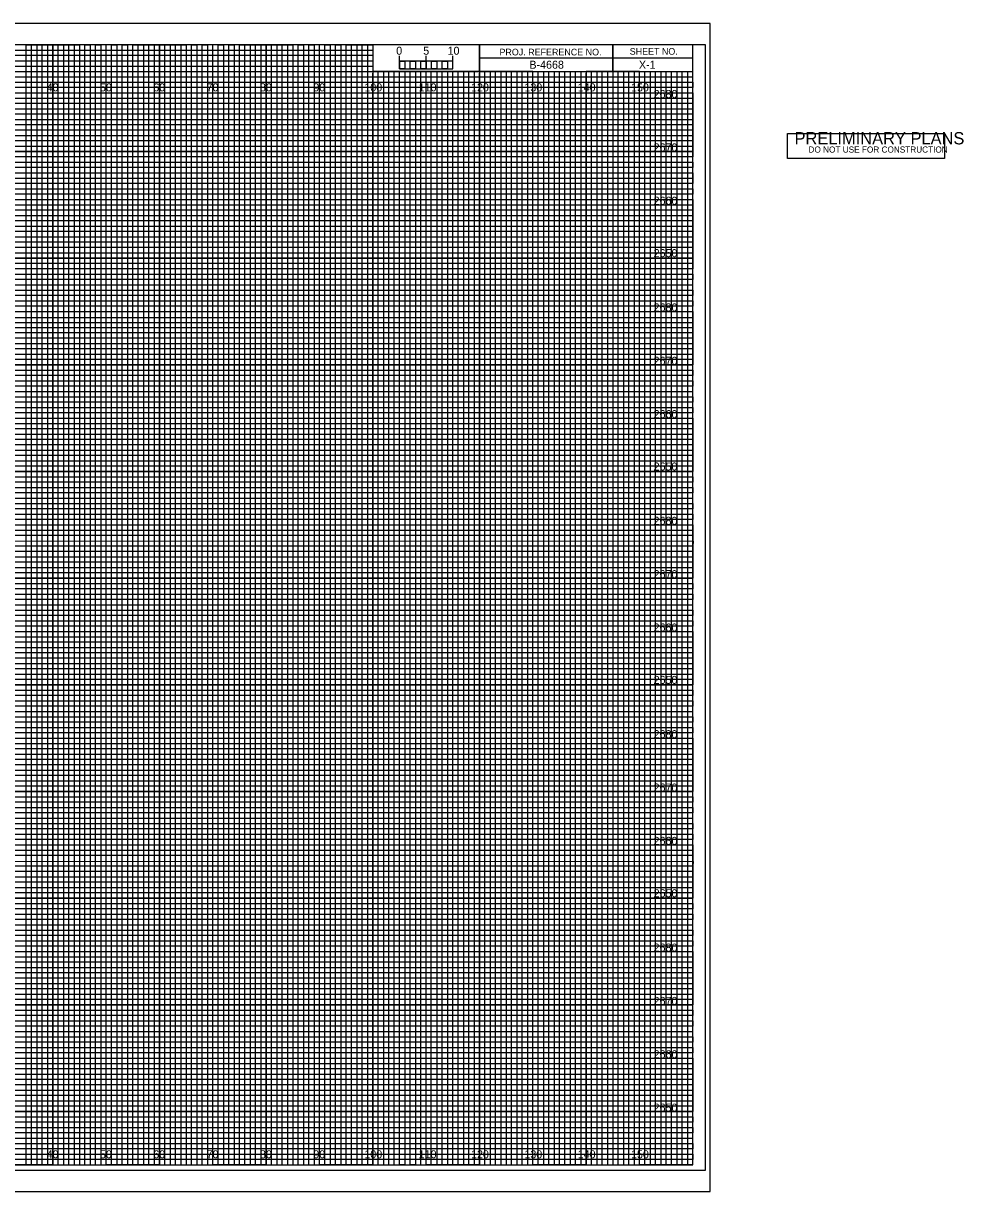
# Model space of a CAD drawing. Extents: x -13 to 371, y -5 to 214.
# Drawn here: x 194.5 to 370.8, y -5 to 214 of the extents above; entities that cross this region are included whole.
import ezdxf

# ---------------------------------------------------------------- set-up
doc = ezdxf.new("R2010")
doc.units = 0
for name, color, linetype in [('Exist Cross Section Cell', 7, 'Continuous'), ('Exist XS Center Line Elevation Label', 7, 'Continuous'), ('Exist XS Ground Line', 7, 'Continuous'), ('Prop XS Bridge', 7, 'Continuous'), ('Prop XS Ditch Slope Text', 7, 'Continuous'), ('Prop XS Ditch Standard Text', 7, 'Continuous'), ('Prop XS Dump Level', 7, 'Continuous'), ('Prop XS EOT Tick Mark', 7, 'Continuous'), ('Prop XS Finish Grade', 7, 'Continuous'), ('Prop XS Finish Grade Earthwork', 7, 'Continuous'), ('Prop XS Pvmt Edge Slope', 7, 'Continuous'), ('Prop XS SE Text', 7, 'Continuous'), ('Prop XS Side Slope Text', 7, 'Continuous'), ('Prop XS SS Elevation Text', 7, 'Continuous'), ('Prop XS Subgrade Earthwork', 7, 'Continuous'), ('Prop XS Vertical Lines', 7, 'Continuous')]:
    doc.layers.add(name, color=color, linetype=linetype)

msp = doc.modelspace()

# ---------------------------------------------------------------- linework, layer by layer
at = {"layer": 'Exist XS Center Line Elevation Label'}
for points in [[(185, 0), (195, 0), (195, 210), (205, 210), (205, 0), (215, 0), (215, 210), (225, 210), (225, 0), (235, 0), (235, 210), (245, 210), (245, 0), (255, 0), (255, 210), (259.93, 210), (260, 210), (260, 205), (264.99, 205), (264.99, 0), (275, 0), (275, 205), (285, 205), (285, 0), (295, 0), (295, 205), (305, 205), (305, 0), (315, 0), (315, 205)], [(0, 205), (275, 205)], [(0, 185), (320, 185), (320, 195), (0, 195)], [(0, 165), (320, 165), (320, 175), (0, 175)], [(0, 145), (320, 145), (320, 155), (0, 155)], [(0, 125), (320, 125), (320, 135), (0, 135)], [(0, 105), (320, 105), (320, 115), (0, 115)], [(0, 85), (320, 85), (320, 95), (0, 95)], [(0, 65), (320, 65), (320, 75), (0, 75)], [(0, 45), (320, 45), (320, 55), (0, 55)], [(0, 25), (320, 25), (320, 35), (0, 35)], [(0, 5), (320, 5), (320, 15), (0, 15)]]:
    msp.add_lwpolyline(points, dxfattribs=at)
at = {"layer": 'Exist XS Ground Line'}
for p, q in [((210, 210), (200, 210)), ((200, 210), (200, 0)), ((210, 0), (210, 210)), ((230, 210), (220, 210)), ((220, 210), (220, 0)), ((230, 0), (230, 210)), ((250, 210), (240, 210)), ((240, 210), (240, 0)), ((250, 0), (250, 210)), ((260, 210), (260, 0)), ((270, 0), (270, 205)), ((290, 205), (280, 205)), ((280, 205), (280, 0)), ((290, 0), (290, 205)), ((310, 205), (300, 205)), ((300, 205), (300, 0)), ((310, 0), (310, 205)), ((200, 0), (190, 0)), ((220, 0), (210, 0)), ((240, 0), (230, 0)), ((260, 0), (250, 0)), ((280, 0), (270, 0)), ((300, 0), (290, 0)), ((320, 0), (310, 0)), ((320, 0), (320, 0))]:
    msp.add_line(p, q, dxfattribs=at)
for points in [[(0, 200), (320, 200), (320, 190), (0, 190)], [(0, 180), (320, 180), (320, 170), (0, 170)], [(0, 160), (320, 160), (320, 150), (0, 150)], [(0, 140), (320, 140), (320, 130), (0, 130)], [(0, 120), (320, 120), (320, 110), (0, 110)], [(0, 100), (320, 100), (320, 90), (0, 90)], [(0, 80), (320, 80), (320, 70), (0, 70)], [(0, 60), (320, 60), (320, 50), (0, 50)], [(0, 40), (320, 40), (320, 30), (0, 30)], [(0, 20), (320, 20), (320, 10), (0, 10)]]:
    msp.add_lwpolyline(points, dxfattribs=at)
at = {"layer": 'Prop XS Ditch Slope Text'}
msp.add_lwpolyline([(-10.8, -1), (322.4, -1), (322.4, 210), (-10.8, 210)], close=True, dxfattribs=at)
at = {"layer": 'Prop XS Ditch Standard Text'}
msp.add_lwpolyline([(-13.4, -5), (323.3, -5), (323.3, 214), (-13.4, 214)], close=True, dxfattribs=at)
at = {"layer": 'Prop XS Dump Level'}
for p, q in [((0, 209), (260, 209)), ((260, 209), (260, 207.98)), ((260, 207.98), (0, 207.98)), ((0, 207), (260, 207)), ((260, 205.89), (0, 205.89)), ((260, 207), (260, 205.89)), ((0, 204), (320, 204))]:
    msp.add_line(p, q, dxfattribs=at)
for points in [[(0, 203), (270, 203), (320, 203), (320, 202), (0, 202)], [(0, 201), (320, 201), (320, 199), (0, 199)], [(0, 198), (320, 198), (320, 197), (0, 196.98)], [(0, 196), (320, 196), (320, 194), (0, 194)], [(0, 193), (320, 193), (320, 192), (0, 192)], [(0, 191), (320, 191), (320, 189), (0, 189)], [(0, 188), (320, 188), (320, 187), (0, 187)], [(0, 186), (320, 186), (320, 184), (0, 184)], [(0, 183), (320, 183), (320, 182), (0, 182)], [(0, 181), (320, 181), (320, 179), (0, 179)], [(0, 178), (320, 178), (320, 177), (0, 177)], [(0, 176), (320, 176), (320, 173.95), (320, 173), (320, 172), (0, 172)], [(0, 174), (320, 174), (320, 173), (0, 173)], [(0, 171), (320, 171), (320, 169), (0, 169.03)], [(0, 169.03), (320, 169), (320, 168), (0, 168)], [(0, 167), (320, 167), (320, 166), (0, 166)], [(0, 164), (320, 164), (320, 163), (0, 163)], [(0, 162), (320, 162), (320, 161), (0, 161)], [(-0.07, 158.89), (320, 158.89), (320, 157.88), (-0.07, 157.88)], [(0, 157), (320, 157), (320, 156), (0, 156)], [(0, 154), (320, 154), (320, 153), (0, 153)], [(0, 152), (320, 152), (320, 151), (0, 151)], [(0, 149), (320, 149), (320, 148), (0, 148)], [(0, 147), (320, 147), (320, 146), (0, 146)], [(0, 144), (320, 144), (320, 143), (0, 143)], [(0, 142), (320, 142), (320, 141), (0, 141)], [(0, 139), (320, 139), (319.99, 137.98), (0, 138)], [(0, 137), (320, 137), (320, 136), (0, 136)], [(0, 134), (320, 134), (320, 133), (0, 133)], [(0, 132), (320, 132), (320, 131), (0, 131)], [(0, 129), (320, 129), (320, 128), (0, 128)], [(0, 127), (320, 127), (320, 126), (0, 126)], [(0, 124), (320, 124), (320, 123), (0, 123)], [(0, 122), (320, 122), (320, 121), (0, 121)], [(0, 119), (320, 119), (320, 118), (0, 118)], [(0, 116.99), (320.07, 116.91), (320, 116), (0, 116)], [(0, 114), (320, 114), (320, 113), (0, 113)], [(0, 112), (320, 112), (320, 111), (0, 111)], [(0, 109), (320, 109), (320, 108), (0, 108)], [(0, 107), (320, 107), (320, 106), (0, 106)], [(0, 104), (320, 104), (320, 103), (0, 103)], [(0, 102), (320, 102), (320, 101), (0, 101)], [(0, 99), (320, 99), (320, 98), (0, 98)], [(0, 97), (320, 97), (320, 96), (0, 96)], [(0, 94), (320, 94), (320, 93), (0, 93)], [(0, 92), (320, 92), (320, 91), (0, 91)], [(0, 89), (320, 89), (320, 88), (0, 88)], [(0, 87), (320, 87), (320, 86), (0, 86)], [(0, 84), (320, 84), (320, 83), (0, 83)], [(0, 82), (320, 82), (320, 81), (0, 81)], [(0, 79), (320, 79), (319.99, 77.98), (0, 78)], [(0, 77), (320, 77), (320, 76), (0, 76)], [(0, 74), (320, 74), (320, 73), (0, 73)], [(0, 72), (320, 72), (320, 71), (0, 71)], [(0, 69), (320, 69), (320, 68), (0, 68)], [(0, 67), (320, 67), (320, 66), (0, 66)], [(0, 64), (320, 64), (320, 63), (0, 63)], [(0, 62), (320, 62), (320, 61), (0, 61)], [(0, 59), (320, 59), (320, 58), (0, 58)], [(0, 56.99), (320.07, 56.91), (320, 56), (0, 56)], [(0, 54), (320, 54), (320, 53), (0, 53)], [(0, 52), (320, 52), (320, 51), (0, 51)], [(0, 49), (320, 49), (320, 48), (0, 48)], [(0, 47), (320, 47), (320, 46), (0, 46)], [(0, 44), (320, 44), (320, 43), (0, 43)], [(0, 42), (320, 42), (320, 41), (0, 41)], [(0, 39), (320, 39), (320, 38), (0, 38)], [(0, 37), (320, 37), (320, 36), (0, 36)], [(0, 34), (320, 34), (320, 33), (0, 33)], [(0, 32), (320, 32), (320, 31), (0, 31)], [(0, 29), (320, 29), (320, 28), (0, 28)], [(0, 27), (320, 27), (320, 26), (0, 26)], [(0, 24), (320, 24), (320, 23), (0, 23)], [(0, 22), (320, 22), (320, 21), (0, 21)], [(0, 19), (320, 19), (320, 18), (0, 18)], [(0, 17), (320, 17), (320, 16), (0, 16)], [(0, 14), (320, 14), (320, 13), (0, 13)], [(0, 12), (320, 12), (320, 11), (0, 11)], [(0, 9), (320, 9), (320, 8), (0, 8)], [(0, 7), (320, 7), (320, 6), (0, 6)], [(0, 4), (320, 4), (320, 3), (0, 3)], [(0, 2), (320, 2), (320, 1), (0, 1)]]:
    msp.add_lwpolyline(points, dxfattribs=at)
at = {"layer": 'Prop XS Finish Grade Earthwork'}
for p, q in [((200, 0), (200, 210)), ((210, 0), (210, 210)), ((220, 0), (220, 210)), ((230, 0), (230, 210)), ((240, 0), (240, 210)), ((250, 0), (250, 210)), ((260, 0), (260, 204.69)), ((270, 0), (270, 204.69)), ((280, 0), (280, 204.69)), ((290, 0), (290, 204.69)), ((300, 0), (300, 204.69)), ((310, 0), (310, 204.69)), ((0, 200), (320, 200)), ((0, 190), (320, 190)), ((0, 180), (320, 180)), ((0, 170), (320, 170)), ((0, 160), (320, 160)), ((0, 150), (320, 150)), ((0, 140), (320, 140)), ((0, 130), (320, 130)), ((0, 120), (320, 120)), ((0, 110), (320, 110)), ((0, 100), (320, 100)), ((0, 90), (320, 90)), ((0, 80), (320, 80)), ((0, 70), (320, 70)), ((0, 60), (320, 60)), ((0, 50), (320, 50)), ((0, 40), (320, 40)), ((0, 30), (320, 30)), ((0, 20), (320, 20)), ((0, 10), (320, 10))]:
    msp.add_line(p, q, dxfattribs=at)
at = {"layer": 'Prop XS SE Text'}
for p, q in [((305, 210), (305, 205)), ((305, 205), (305, 210)), ((280, 207.5), (280, 205)), ((320, 207.49), (280, 207.49)), ((280, 205), (320, 205))]:
    msp.add_line(p, q, dxfattribs=at)
for points in [[(320, 210), (0, 210), (0, 0), (320, 0)], [(280, 210), (260, 210), (260, 205.03), (280, 205.03)], [(320, 210), (280, 210), (280, 205), (320, 205)]]:
    msp.add_lwpolyline(points, close=True, dxfattribs=at)
at = {"layer": 'Prop XS Side Slope Text'}
for p, q in [((267, 205), (266.01, 205)), ((266.01, 205), (266.01, 0)), ((267, 0), (267, 205)), ((269, 205), (268, 205)), ((268, 205), (268, 0)), ((269, 0), (269, 205)), ((266.01, 0), (265, 0)), ((268, 0), (267, 0))]:
    msp.add_line(p, q, dxfattribs=at)
for points in [[(195, 0), (196, 0), (196, 210), (197, 210), (197, 0)], [(197, 0), (198, 0), (198, 210), (199, 210), (199, 0)], [(200, 0), (201, 0), (201, 210), (202, 210), (202, 0)], [(202, 0), (203, 0), (203, 210), (204, 210), (204, 0)], [(205, 0), (206, 0), (206, 210), (207, 210), (207, 0)], [(207, 0), (208, 0), (208, 210), (209, 210), (209, 0)], [(210, 0), (211, 0), (211, 210), (212, 210), (212, 0)], [(212, 0), (213, 0), (213, 210), (214, 210), (214, 0)], [(215, 0), (216, 0), (216, 210), (217, 210), (217, 0)], [(217, 0), (218, 0), (218, 210), (219, 210), (219, 0)], [(220, 0), (221, 0), (221, 210), (222, 210), (222, 0)], [(222, 0), (223, 0), (223, 210), (224, 210), (224, 0)], [(225, 0), (226, 0), (226, 210), (227, 210), (227, 0)], [(227, 0), (228, 0), (228, 210), (229, 210), (229, 0)], [(230, 0), (231, 0), (231, 210), (232, 210), (232, 0)], [(232, 0), (233, 0), (233, 210), (234, 210), (234, 0)], [(235, 0), (236, 0), (236, 210), (237, 210), (237, 0)], [(237, 0), (238, 0), (238, 210), (239, 210), (239, 0)], [(240, 0), (241, 0), (241, 210), (242, 210), (242, 0)], [(242, 0), (243, 0), (243, 210), (244, 210), (244, 0)], [(245, 0), (246, 0), (246, 210), (247, 210), (247, 0)], [(247, 0), (248, 0), (248, 210), (249, 210), (249, 0)], [(250, 0), (251, 0), (251, 210), (252, 210), (252, 0)], [(252, 0), (253, 0), (253, 210), (254, 210), (254, 0)], [(255, 0), (256, 0), (256, 210), (257, 210), (257, 0)], [(257, 0), (258, 0), (258, 210), (259, 210), (259, 0)], [(260, 0), (261, 0), (261, 205), (262.02, 205), (262.02, 0)], [(262, 0), (263, 0), (263, 205), (263.99, 205), (263.99, 0)], [(270, 0), (270.98, 0), (270.98, 205), (272, 205), (272, 0)], [(272, 0), (273, 0), (273, 205), (274.05, 205), (274.05, 0)], [(275, 0), (276, 0), (276, 205), (277, 205), (277, 0)], [(277, 0), (278, 0), (278, 205), (279, 205), (279, 0)], [(280, 0), (281, 0), (281, 205), (282, 205), (282, 0)], [(282, 0), (283, 0), (283, 205), (284, 205), (284, 0)], [(285, 0), (286, 0), (286, 205), (287, 205), (287, 0)], [(287, 0), (288, 0), (288, 205), (289, 205), (289, 0)], [(290, 0), (291, 0), (291, 205), (292, 205), (292, 0)], [(292, 0), (293, 0), (293, 205), (294, 205), (294, 0)], [(295, 0), (296, 0), (296, 205), (297, 205), (297, 0)], [(297, 0), (298, 0), (298, 205), (299, 205), (299, 0)], [(300, 0), (301, 0), (301, 205), (302, 205), (302, 0)], [(302, 0), (303, 0), (303, 205), (304, 205), (304, 0)], [(305, 0), (306, 0), (306, 205), (307, 205), (307, 0)], [(307, 0), (308, 0), (308, 205), (309, 205), (309, 0)], [(310, 0), (311, 0), (311, 205), (312, 205), (312, 0)], [(312, 0), (313, 0), (313, 205), (314, 205), (314, 0)], [(315, 0), (316, 0), (316, 205), (317, 205), (317, 0)], [(317, 0), (318, 0), (318, 205), (319, 205), (319, 0)]]:
    msp.add_lwpolyline(points, dxfattribs=at)
at = {"layer": 'Prop XS SS Elevation Text'}
for p, q in [((265, 205.49), (265, 207.9)), ((265, 206.9), (265, 207.9)), ((270, 205.49), (270, 207.9)), ((275, 205.49), (275, 207.9)), ((275, 206.9), (275, 207.9))]:
    msp.add_line(p, q, dxfattribs=at)
for points in [[(275, 206.9), (265, 206.9), (265, 205.49), (275, 205.49)], [(265, 206.9), (266, 206.9), (266, 205.49), (265, 205.49)], [(267, 206.9), (268, 206.9), (268, 205.49), (267, 205.49)], [(269, 206.9), (270, 206.9), (270, 205.49), (269, 205.49)], [(271, 206.9), (272, 206.9), (272, 205.49), (271, 205.49)], [(273, 206.9), (274, 206.9), (274, 205.49), (273, 205.49)]]:
    msp.add_lwpolyline(points, close=True, dxfattribs=at)
at = {"layer": 'Prop XS Subgrade Earthwork'}
for p, q in [((323.3, 214), (-13.4, 214)), ((-13.4, -5), (323.3, -5))]:
    msp.add_line(p, q, dxfattribs=at)
at = {"layer": 'Prop XS Vertical Lines'}
msp.add_lwpolyline([(337.79, 188.68), (337.79, 193.38), (367.19, 193.38), (367.19, 188.68)], close=True, dxfattribs=at)

# ---------------------------------------------------------------- texts
at = {"layer": 'Exist Cross Section Cell'}
for s, p in [('40', (198.86, 201.25)), ('50', (208.86, 201.25)), ('60', (218.86, 201.25)), ('70', (228.86, 201.25)), ('80', (238.86, 201.25)), ('90', (248.86, 201.25)), ('100', (258.44, 201.25)), ('110', (268.62, 201.25)), ('120', (278.44, 201.25)), ('130', (288.44, 201.25)), ('140', (298.44, 201.25)), ('150', (308.44, 201.25)), ('40', (198.86, 1.25)), ('50', (208.86, 1.25)), ('60', (218.86, 1.25)), ('70', (228.86, 1.25)), ('80', (238.86, 1.25)), ('90', (248.86, 1.25)), ('100', (258.44, 1.25)), ('110', (268.62, 1.25)), ('120', (278.44, 1.25)), ('130', (288.44, 1.25)), ('140', (298.44, 1.25)), ('150', (308.44, 1.25))]:
    msp.add_text(s, height=1.5, dxfattribs=at).set_placement(p)
at = {"layer": 'Prop XS Bridge'}
for s, p in [('5', (269.47, 208.12)), ('10', (274.04, 208.12))]:
    msp.add_text(s, height=1.5, dxfattribs=at).set_placement(p)
at = {"layer": 'Prop XS EOT Tick Mark'}
msp.add_text('B-4668', height=1.5, dxfattribs=at).set_placement((289.38, 205.5))
at = {"layer": 'Prop XS Finish Grade'}
for s, p in [('2680', (312.67, 200)), ('2670', (312.67, 190)), ('2660', (312.67, 180)), ('2650', (312.67, 170.18)), ('2680', (312.67, 160)), ('2670', (312.67, 150)), ('2660', (312.67, 140)), ('2650', (312.67, 130.18)), ('2680', (312.67, 120)), ('2670', (312.67, 110)), ('2660', (312.67, 100)), ('2650', (312.67, 90.18)), ('2680', (312.67, 80)), ('2670', (312.67, 70)), ('2660', (312.67, 60)), ('2650', (312.67, 50.18)), ('2680', (312.67, 40)), ('2670', (312.67, 30)), ('2660', (312.67, 20)), ('2650', (312.67, 10))]:
    msp.add_text(s, height=1.5, dxfattribs=at).set_placement(p)
at = {"layer": 'Prop XS Pvmt Edge Slope'}
msp.add_text('X-1', height=1.5, dxfattribs=at).set_placement((309.91, 205.5))
at = {"layer": 'Prop XS SE Text'}
for s, p in [('PROJ. REFERENCE NO.', (283.77, 207.99)), ('SHEET NO.', (308.19, 208.12))]:
    msp.add_text(s, height=1.25, dxfattribs=at).set_placement(p)
at = {"layer": 'Prop XS SS Elevation Text'}
msp.add_text('0', height=1.5, dxfattribs=at).set_placement((264.41, 208.12))
at = {"layer": 'Prop XS Vertical Lines'}
for s, height, p in [('PRELIMINARY PLANS', 2.304, (339.09, 191.31)), ('DO NOT USE FOR CONSTRUCTION', 1.152, (341.71, 189.77))]:
    msp.add_text(s, height=height, dxfattribs=at).set_placement(p)

doc.saveas('drawing.dxf')
